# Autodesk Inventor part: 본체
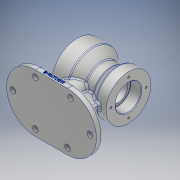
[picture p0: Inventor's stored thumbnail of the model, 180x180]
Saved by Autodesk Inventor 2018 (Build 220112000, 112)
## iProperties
Created: 2020-01
Part Number: 본체
Material: 알루미늄 6061
Document SubType Name: Modeling
Designer: Administrator
Density: 2.7 g/cm^3
Appearance: 알루미늄 - 평지
Mass: 938.141 g
Surface Area: 654.845 cm^2
Volume: 347.46 cm^3
Author: Administrator
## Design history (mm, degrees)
sketch "스케치1"
  geometry: L1 (0, 0)-(24, 0); L2 (24, 0)-(24, 40); L3 (24, 40)-(0, 40); L4 (0, 40)-(0, 0); L5 (24, 0)-(33.358, 0); L6 (24, 28.653)-(24, 0); L7 (33.358, 0)-(53.289, 0); L8 (53.289, 0)-(53.289, 27.5); L9 (53.289, 0)-(64, 0); L10 (64, 0)-(64, 27.491); L11 (53.289, 27.5)-(53.289, 0); L12 (64, 0)-(80, 0); L13 (80, 0)-(80, 35); L14 (80, 35)-(64, 35); L15 (64, 35)-(64, 0); L16 (24, 40)-(38.897, 27.5); L17 (64, 35)-(53.289, 27.5); L18 (53.289, 27.5)-(38.897, 27.5); L19 (38.897, 27.5)-(38.897, 0)
  constraints: 38 end point, 5 horizontal, 5 parallel, 5 perpendicular, 1 point on line
  dimensions: "d0" = 80 distance between parallel lines of L13 L4; "d1" = 24 distance between parallel lines of L6 L4; "d2" = 16 distance between parallel lines of L13 L10; "d6" = 40 deg angle of L18 L16; "d7" = 35 deg angle of L17 L18; "d8" = 80 diameter of L3 L1; "d9" = 70 diameter of L14 L12; "d41" = 55 diameter of L18 L7
revolve "회전1" sketch "스케치1" stored, may be unused: angle "d10" = 90 deg
sketch "스케치2"
  geometry: L1 (40, 0)-(40, -80); L2 (0, -40)-(0, 40) reference; L3 (-30, -70)-(110, -70); L4 (110, -70)-(110, -80); L5 (110, -80)-(-30, -80); L6 (-30, -80)-(-30, -70); 1 further point
  constraints: 10 end point, 2 parallel, 1 horizontal, 1 perpendicular, 1 vertical
  dimensions: "d11" = 80 distance of L1.start L1.end; "d12" = 40 distance between parallel lines of L1 L2; "d13" = 140 distance between parallel lines of L4 L6; "d14" = 70 distance between parallel lines of L1 L6; "d68" = 10 distance between parallel lines of L5 L3; "d70" = 80 distance from line of point (0, 0) L5
extrude "돌출1" join sketch "스케치2" stored distance "d15" = 90; taper "d16" = 0 deg
fillet "모깎기1" dims "d17" = 45
sketch "스케치3"
  geometry: L1 (0, 0)-(50, 0) reference; L2 (50, -90)-(0, -90) reference; L3 (28.199, -40)-(55, -40); L4 (28.199, -50)-(55, -50); L5 (55, -40)-(55, -50); L6 (55, -79.641)-(55, -80); C1 r 4.5 at (0, -10); C2 r 4.5 at (50, -10); C3 r 4.5 at (85, -45); C4 r 4.5 at (55, -79.641); C5 r 4.5 at (0, -80); C6 r 4.5 at (-35, -45); A1 r 45 centre (50, -45) between (50, -90) and (50, 0) reference; A2 r 45 centre (0, -45) between (0, 0) and (0, -90) reference; A3 r 16 centre (13, -45) between (28.199, -40) and (28.199, -50); 1 further point
  constraints: 8 end point, 7 centre point, 2 point on circle, 1 coincident
  dimensions: "d20" = 32 diameter of A3; "d24" = 9 diameter of C1; "d25" = 9 diameter of C2; "d26" = 9 diameter of C3; "d27" = 9 diameter of C4; "d28" = 9 diameter of C5; "d29" = 9 diameter of C6
extrude "돌출2" cut sketch "스케치3" distance "d30" = 90; taper "d31" = 0 deg
extrude "돌출3" join sketch "스케치3" stored distance "d32" = 90; taper "d33" = 0 deg
sketch "스케치4"
  geometry: L1 (0, 0)-(20, 0); L2 (20, 0)-(20, 25.7); L3 (19.7, 26)-(0, 26); L4 (0, 26)-(0, 0); L5 (20, 0)-(63, 0); L6 (63, 0)-(63, 16); L7 (63, 16)-(20, 16); L8 (20, 16)-(20, 0); L9 (80, -35)-(80, 35) reference; L10 (63, 0)-(80, 0); L11 (80, 0)-(80, 20); L12 (80, 20)-(63.3, 20); L13 (63, 19.7)-(63, 0); A1 r 0.3 centre (63.3, 19.7) between (63.3, 20) and (63, 19.7); A2 r 0.3 centre (19.7, 25.7) between (20, 25.7) and (19.7, 26)
  constraints: 24 end point, 6 parallel, 4 point on circle, 4 tangent, 3 horizontal, 3 perpendicular, 2 centre point, 1 equal radius, 1 point on line
  dimensions: "d34" = 17 distance between parallel lines of L9 L6; "d35" = 20 distance between parallel lines of L2 L4; "d36" = 52 diameter of L3 L1; "d37" = 32 diameter of L7 L5; "d38" = 40 diameter of L12 L10; "d39" = 0.3 radius of A1
revolve "회전2" sketch "스케치4" stored, may be unused: angle "d40" = 90 deg
sketch "스케치5"
  geometry: A1 r 33 centre (0, 0) between (0, 33) and (33, 0); 3 further points
  constraints: 4 point on circle, 1 centre point, 1 coincident
  dimensions: "d42" = 66 diameter of A1
hole "구멍1" sketch "스케치5" at (0, 33), (33, 0), (-33, 0), (0, -33) diameter "d43" = 3.242; stored, may be unused: countersink angle "d47" = 90 deg, drill point angle "d49" = 118 deg; dims "d44" = 9, "d45" = 4, "d46" = 2, "d48" = 11
sketch "스케치6"
  geometry: A1 r 27.5 centre (0, 0) between (0, 27.5) and (27.5, 0); 3 further points
  constraints: 4 point on circle, 1 centre point, 1 coincident
  dimensions: "d50" = 55 diameter of A1
hole "구멍2" sketch "스케치6" at (0, 27.5), (27.5, 0), (-27.5, 0), (0, -27.5) diameter "d51" = 3.242; stored, may be unused: countersink angle "d55" = 90 deg, drill point angle "d57" = 118 deg; dims "d52" = 9, "d53" = 4, "d54" = 2, "d56" = 11
sketch "스케치7"
  geometry: L1 (-30, -70)-(15, -70) reference; L2 (110, -80)-(65, -80) reference; 2 further points
  constraints: 1 other
  dimensions: "d58" = 70 horizontal distance of point (40, -76) L1.start; "d59" = 4 distance from line of point (40, -76) L2
feature "엠보싱1" sketch "스케치7" dims "d60" = 0.5, "d61" = 0
chamfer "모따기1" distance "d62" = 1; stored, may be unused: second distance "d63" = 2, angle "d64" = 45 deg
fillet "모깎기2" dims "d65" = 3
fillet "모깎기3" dims "d66" = 3
fillet "모깎기4" dims "d67" = 3
fillet "모깎기5" dims "d69" = 3
fillet "모깎기6" dims "d71" = 3
node "솔리드1"
